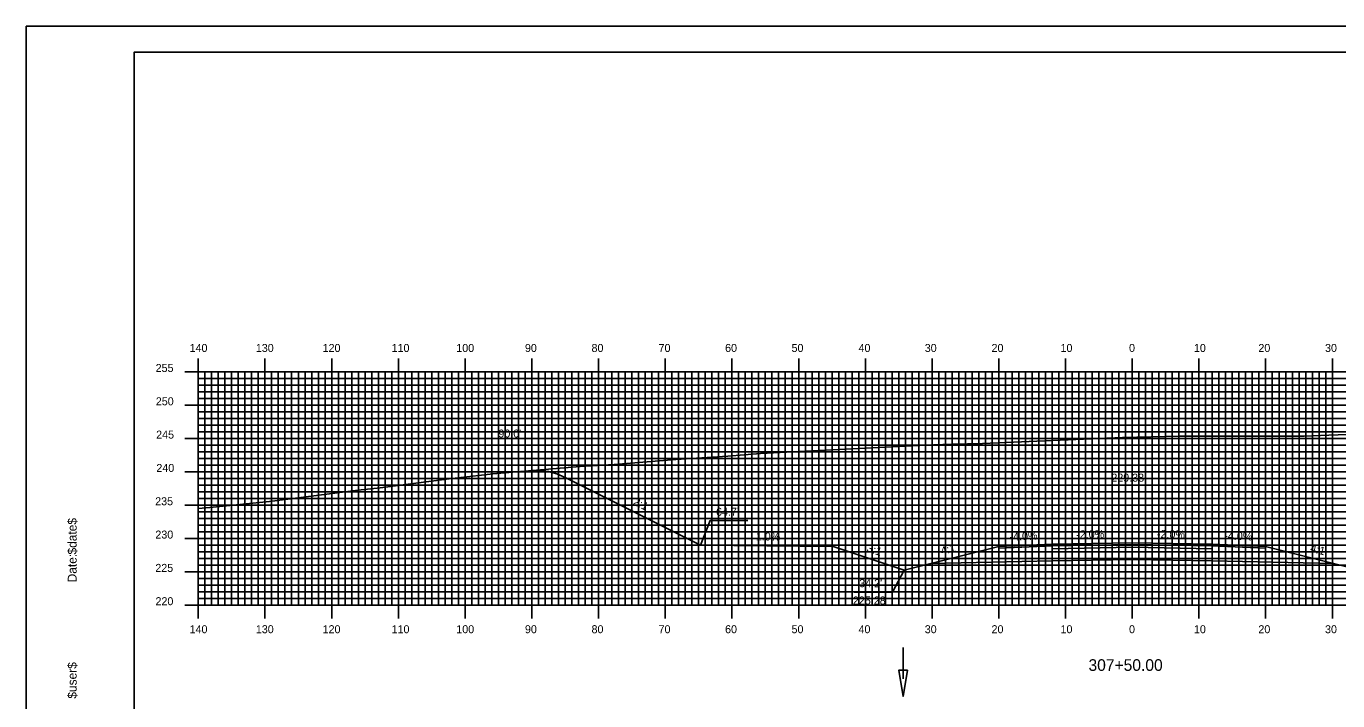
# Model space of a CAD drawing. Extents: x 1817276 to 1817620, y 442591 to 442811.
# Drawn here: x 1817276.3 to 1817472.9, y 442709.3 to 442810.5 of the extents above; entities that cross this region are included whole.
import ezdxf

# ---------------------------------------------------------------- set-up
doc = ezdxf.new("R2010")
doc.units = 0
for name, color, linetype in [('ANNOTATION', 7, 'Continuous'), ('BORDER', 7, 'Continuous'), ('D_Drainage_Ditch_Line', 7, 'Continuous'), ('D_Roadway_Centerline', 7, 'Continuous'), ('D_Roadway_Centerline_Text', 7, 'Continuous'), ('D_Roadway_Edge_Shoulder', 7, 'Continuous'), ('D_Roadway_Edge_TW', 7, 'Continuous'), ('D_Roadway_Pavement', 7, 'Continuous'), ('D_Roadway_SlopeLines', 7, 'Continuous'), ('D_Roadway_SubGrade', 7, 'Continuous'), ('D_Text_Standard', 7, 'Continuous'), ('H_V ANNOTATION', 7, 'Continuous'), ('MAJOR', 7, 'Continuous'), ('MINOR', 7, 'Continuous'), ('PLOT BOUNDARY', 7, 'Continuous'), ('S_Roadway_Centerline', 7, 'Continuous')]:
    doc.layers.add(name, color=color, linetype=linetype)

msp = doc.modelspace()

# ---------------------------------------------------------------- linework, layer by layer
at = {"layer": 'ANNOTATION'}
for points in [[(1817384.5, 442736.36), (1817378.81, 442736.36), (1817377.4, 442732.69)], [(1817400.44, 442725.65), (1817406.14, 442725.65), (1817407.93, 442728.94)]]:
    msp.add_lwpolyline(points, dxfattribs=at)
at = {"layer": 'BORDER'}
msp.add_lwpolyline([(1817292.5, 442596.67), (1817612.5, 442596.67), (1817612.5, 442806.67), (1817292.5, 442806.67)], close=True, dxfattribs=at)
at = {"layer": 'D_Drainage_Ditch_Line'}
msp.add_line((1817407.75, 442712.61), (1817407.75, 442717.31), dxfattribs=at)
msp.add_lwpolyline([(1817408.41, 442713.92), (1817407.1, 442713.92), (1817407.75, 442709.99)], close=True, dxfattribs=at)
at = {"layer": 'D_Roadway_Centerline'}
msp.add_lwpolyline([(1817352.1, 442743.88), (1817353.35, 442743.89), (1817354.6, 442743.72), (1817355.85, 442743.37), (1817357.1, 442742.84), (1817377.4, 442732.69), (1817397.29, 442732.49), (1817407.93, 442728.94), (1817411.93, 442729.94), (1817422.1, 442732.49), (1817430.1, 442732.81), (1817442.1, 442733.05), (1817454.1, 442732.81), (1817462.1, 442732.49), (1817472.27, 442729.94), (1817476.27, 442728.94), (1817486.9, 442732.49), (1817495.76, 442732.58), (1817527.1, 442748.25), (1817528.35, 442748.79), (1817529.6, 442749.19), (1817530.85, 442749.43), (1817532.1, 442749.51)], dxfattribs=at)
at = {"layer": 'D_Roadway_Edge_Shoulder'}
for points in [[(1817430.1, 442732.81), (1817422.1, 442732.49), (1817422.1, 442732.24), (1817430.1, 442732.56)], [(1817454.1, 442732.81), (1817462.1, 442732.49), (1817462.1, 442732.24), (1817454.1, 442732.56)]]:
    msp.add_lwpolyline(points, close=True, dxfattribs=at)
at = {"layer": 'D_Roadway_Edge_TW'}
msp.add_lwpolyline([(1817430.1, 442732.56), (1817430.1, 442732.81), (1817442.1, 442733.05), (1817454.1, 442732.81), (1817454.1, 442732.56), (1817442.1, 442732.8)], close=True, dxfattribs=at)
at = {"layer": 'D_Roadway_Pavement'}
msp.add_lwpolyline([(1817430.1, 442732.14), (1817430.1, 442732.56), (1817442.1, 442732.8), (1817454.1, 442732.56), (1817454.1, 442732.14), (1817442.1, 442732.38)], close=True, dxfattribs=at)
at = {"layer": 'D_Roadway_SlopeLines'}
for points in [[(1817397.29, 442732.49), (1817377.4, 442732.69), (1817357.1, 442742.84), (1817355.85, 442743.37), (1817354.6, 442743.72), (1817353.35, 442743.89), (1817352.1, 442743.88)], [(1817407.93, 442728.94), (1817397.29, 442732.49)], [(1817422.1, 442732.49), (1817407.93, 442728.94)], [(1817462.1, 442732.49), (1817476.27, 442728.94)]]:
    msp.add_lwpolyline(points, dxfattribs=at)
at = {"layer": 'D_Roadway_SubGrade'}
msp.add_lwpolyline([(1817430.1, 442730.31), (1817411.93, 442729.94), (1817422.1, 442732.49), (1817422.1, 442732.24), (1817430.1, 442732.56), (1817442.1, 442732.8), (1817454.1, 442732.56), (1817462.1, 442732.24), (1817462.1, 442732.49), (1817472.27, 442729.94), (1817454.1, 442730.31), (1817442.1, 442730.55)], close=True, dxfattribs=at)
at = {"layer": 'MAJOR'}
for p, q in [((1817302.1, 442760.67), (1817302.1, 442758.67)), ((1817312.1, 442760.67), (1817312.1, 442758.67)), ((1817322.1, 442760.67), (1817322.1, 442758.67)), ((1817332.1, 442760.67), (1817332.1, 442758.67)), ((1817342.1, 442760.67), (1817342.1, 442758.67)), ((1817352.1, 442760.67), (1817352.1, 442758.67)), ((1817362.1, 442760.67), (1817362.1, 442758.67)), ((1817372.1, 442760.67), (1817372.1, 442758.67)), ((1817382.1, 442760.67), (1817382.1, 442758.67)), ((1817392.1, 442760.67), (1817392.1, 442758.67)), ((1817402.1, 442760.67), (1817402.1, 442758.67)), ((1817412.1, 442760.67), (1817412.1, 442758.67)), ((1817422.1, 442760.67), (1817422.1, 442758.67)), ((1817432.1, 442760.67), (1817432.1, 442758.67)), ((1817442.1, 442760.67), (1817442.1, 442758.67)), ((1817452.1, 442760.67), (1817452.1, 442758.67)), ((1817462.1, 442760.67), (1817462.1, 442758.67)), ((1817472.1, 442760.67), (1817472.1, 442758.67)), ((1817300.1, 442758.67), (1817302.1, 442758.67)), ((1817302.1, 442758.67), (1817582.1, 442758.67)), ((1817302.1, 442723.67), (1817302.1, 442758.67)), ((1817302.1, 442723.67), (1817302.1, 442758.67)), ((1817302.1, 442758.67), (1817582.1, 442758.67)), ((1817312.1, 442723.67), (1817312.1, 442758.67)), ((1817322.1, 442723.67), (1817322.1, 442758.67)), ((1817332.1, 442723.67), (1817332.1, 442758.67)), ((1817342.1, 442723.67), (1817342.1, 442758.67)), ((1817352.1, 442723.67), (1817352.1, 442758.67)), ((1817362.1, 442723.67), (1817362.1, 442758.67)), ((1817372.1, 442723.67), (1817372.1, 442758.67)), ((1817382.1, 442723.67), (1817382.1, 442758.67)), ((1817392.1, 442723.67), (1817392.1, 442758.67)), ((1817402.1, 442723.67), (1817402.1, 442758.67)), ((1817412.1, 442723.67), (1817412.1, 442758.67)), ((1817422.1, 442723.67), (1817422.1, 442758.67)), ((1817432.1, 442723.67), (1817432.1, 442758.67)), ((1817442.1, 442723.67), (1817442.1, 442758.67)), ((1817452.1, 442723.67), (1817452.1, 442758.67)), ((1817462.1, 442723.67), (1817462.1, 442758.67)), ((1817472.1, 442723.67), (1817472.1, 442758.67)), ((1817300.1, 442753.67), (1817302.1, 442753.67)), ((1817302.1, 442753.67), (1817582.1, 442753.67)), ((1817300.1, 442748.67), (1817302.1, 442748.67)), ((1817302.1, 442748.67), (1817582.1, 442748.67)), ((1817300.1, 442743.67), (1817302.1, 442743.67)), ((1817302.1, 442743.67), (1817582.1, 442743.67)), ((1817300.1, 442738.67), (1817302.1, 442738.67)), ((1817302.1, 442738.67), (1817582.1, 442738.67)), ((1817300.1, 442733.67), (1817302.1, 442733.67)), ((1817302.1, 442733.67), (1817582.1, 442733.67)), ((1817300.1, 442728.67), (1817302.1, 442728.67)), ((1817302.1, 442728.67), (1817582.1, 442728.67)), ((1817300.1, 442723.67), (1817302.1, 442723.67)), ((1817302.1, 442723.67), (1817582.1, 442723.67)), ((1817302.1, 442723.67), (1817582.1, 442723.67)), ((1817302.1, 442721.66), (1817302.1, 442723.67)), ((1817312.1, 442721.66), (1817312.1, 442723.67)), ((1817322.1, 442721.66), (1817322.1, 442723.67)), ((1817332.1, 442721.66), (1817332.1, 442723.67)), ((1817342.1, 442721.66), (1817342.1, 442723.67)), ((1817352.1, 442721.66), (1817352.1, 442723.67)), ((1817362.1, 442721.66), (1817362.1, 442723.67)), ((1817372.1, 442721.66), (1817372.1, 442723.67)), ((1817382.1, 442721.66), (1817382.1, 442723.67)), ((1817392.1, 442721.66), (1817392.1, 442723.67)), ((1817402.1, 442721.66), (1817402.1, 442723.67)), ((1817412.1, 442721.66), (1817412.1, 442723.67)), ((1817422.1, 442721.66), (1817422.1, 442723.67)), ((1817432.1, 442721.66), (1817432.1, 442723.67)), ((1817442.1, 442721.66), (1817442.1, 442723.67)), ((1817452.1, 442721.66), (1817452.1, 442723.67)), ((1817462.1, 442721.66), (1817462.1, 442723.67)), ((1817472.1, 442721.66), (1817472.1, 442723.67))]:
    msp.add_line(p, q, dxfattribs=at)
at = {"layer": 'MINOR'}
for p, q in [((1817302.1, 442757.67), (1817582.1, 442757.67)), ((1817302.1, 442757.67), (1817304.1, 442757.67)), ((1817303.1, 442723.67), (1817303.1, 442758.67)), ((1817304.1, 442723.67), (1817304.1, 442758.67)), ((1817305.1, 442723.67), (1817305.1, 442758.67)), ((1817306.1, 442723.67), (1817306.1, 442758.67)), ((1817307.1, 442723.67), (1817307.1, 442758.67)), ((1817308.1, 442723.67), (1817308.1, 442758.67)), ((1817309.1, 442723.67), (1817309.1, 442758.67)), ((1817310.1, 442723.67), (1817310.1, 442758.67)), ((1817311.1, 442723.67), (1817311.1, 442758.67)), ((1817313.1, 442723.67), (1817313.1, 442758.67)), ((1817314.1, 442723.67), (1817314.1, 442758.67)), ((1817315.1, 442723.67), (1817315.1, 442758.67)), ((1817316.1, 442723.67), (1817316.1, 442758.67)), ((1817317.1, 442723.67), (1817317.1, 442758.67)), ((1817318.1, 442723.67), (1817318.1, 442758.67)), ((1817319.1, 442723.67), (1817319.1, 442758.67)), ((1817320.1, 442723.67), (1817320.1, 442758.67)), ((1817321.1, 442723.67), (1817321.1, 442758.67)), ((1817323.1, 442723.67), (1817323.1, 442758.67)), ((1817324.1, 442723.67), (1817324.1, 442758.67)), ((1817325.1, 442723.67), (1817325.1, 442758.67)), ((1817326.1, 442723.67), (1817326.1, 442758.67)), ((1817327.1, 442723.67), (1817327.1, 442758.67)), ((1817328.1, 442723.67), (1817328.1, 442758.67)), ((1817329.1, 442723.67), (1817329.1, 442758.67)), ((1817330.1, 442723.67), (1817330.1, 442758.67)), ((1817331.1, 442723.67), (1817331.1, 442758.67)), ((1817333.1, 442723.67), (1817333.1, 442758.67)), ((1817334.1, 442723.67), (1817334.1, 442758.67)), ((1817335.1, 442723.67), (1817335.1, 442758.67)), ((1817336.1, 442723.67), (1817336.1, 442758.67)), ((1817337.1, 442723.67), (1817337.1, 442758.67)), ((1817338.1, 442723.67), (1817338.1, 442758.67)), ((1817339.1, 442723.67), (1817339.1, 442758.67)), ((1817340.1, 442723.67), (1817340.1, 442758.67)), ((1817341.1, 442723.67), (1817341.1, 442758.67)), ((1817343.1, 442723.67), (1817343.1, 442758.67)), ((1817344.1, 442723.67), (1817344.1, 442758.67)), ((1817345.1, 442723.67), (1817345.1, 442758.67)), ((1817346.1, 442723.67), (1817346.1, 442758.67)), ((1817347.1, 442723.67), (1817347.1, 442758.67)), ((1817348.1, 442723.67), (1817348.1, 442758.67)), ((1817349.1, 442723.67), (1817349.1, 442758.67)), ((1817350.1, 442723.67), (1817350.1, 442758.67)), ((1817351.1, 442723.67), (1817351.1, 442758.67)), ((1817353.1, 442723.67), (1817353.1, 442758.67)), ((1817354.1, 442723.67), (1817354.1, 442758.67)), ((1817355.1, 442723.67), (1817355.1, 442758.67)), ((1817356.1, 442723.67), (1817356.1, 442758.67)), ((1817357.1, 442723.67), (1817357.1, 442758.67)), ((1817358.1, 442723.67), (1817358.1, 442758.67)), ((1817359.1, 442723.67), (1817359.1, 442758.67)), ((1817360.1, 442723.67), (1817360.1, 442758.67)), ((1817361.1, 442723.67), (1817361.1, 442758.67)), ((1817363.1, 442723.67), (1817363.1, 442758.67)), ((1817364.1, 442723.67), (1817364.1, 442758.67)), ((1817365.1, 442723.67), (1817365.1, 442758.67)), ((1817366.1, 442723.67), (1817366.1, 442758.67)), ((1817367.1, 442723.67), (1817367.1, 442758.67)), ((1817368.1, 442723.67), (1817368.1, 442758.67)), ((1817369.1, 442723.67), (1817369.1, 442758.67)), ((1817370.1, 442723.67), (1817370.1, 442758.67)), ((1817371.1, 442723.67), (1817371.1, 442758.67)), ((1817373.1, 442723.67), (1817373.1, 442758.67)), ((1817374.1, 442723.67), (1817374.1, 442758.67)), ((1817375.1, 442723.67), (1817375.1, 442758.67)), ((1817376.1, 442723.67), (1817376.1, 442758.67)), ((1817377.1, 442723.67), (1817377.1, 442758.67)), ((1817378.1, 442723.67), (1817378.1, 442758.67)), ((1817379.1, 442723.67), (1817379.1, 442758.67)), ((1817380.1, 442723.67), (1817380.1, 442758.67)), ((1817381.1, 442723.67), (1817381.1, 442758.67)), ((1817383.1, 442723.67), (1817383.1, 442758.67)), ((1817384.1, 442723.67), (1817384.1, 442758.67)), ((1817385.1, 442723.67), (1817385.1, 442758.67)), ((1817386.1, 442723.67), (1817386.1, 442758.67)), ((1817387.1, 442723.67), (1817387.1, 442758.67)), ((1817388.1, 442723.67), (1817388.1, 442758.67)), ((1817389.1, 442723.67), (1817389.1, 442758.67)), ((1817390.1, 442723.67), (1817390.1, 442758.67)), ((1817391.1, 442723.67), (1817391.1, 442758.67)), ((1817393.1, 442723.67), (1817393.1, 442758.67)), ((1817394.1, 442723.67), (1817394.1, 442758.67)), ((1817395.1, 442723.67), (1817395.1, 442758.67)), ((1817396.1, 442723.67), (1817396.1, 442758.67)), ((1817397.1, 442723.67), (1817397.1, 442758.67)), ((1817398.1, 442723.67), (1817398.1, 442758.67)), ((1817399.1, 442723.67), (1817399.1, 442758.67)), ((1817400.1, 442723.67), (1817400.1, 442758.67)), ((1817401.1, 442723.67), (1817401.1, 442758.67)), ((1817403.1, 442723.67), (1817403.1, 442758.67)), ((1817404.1, 442723.67), (1817404.1, 442758.67)), ((1817405.1, 442723.67), (1817405.1, 442758.67)), ((1817406.1, 442723.67), (1817406.1, 442758.67)), ((1817407.1, 442723.67), (1817407.1, 442758.67)), ((1817408.1, 442723.67), (1817408.1, 442758.67)), ((1817409.1, 442723.67), (1817409.1, 442758.67)), ((1817410.1, 442723.67), (1817410.1, 442758.67)), ((1817411.1, 442723.67), (1817411.1, 442758.67)), ((1817413.1, 442723.67), (1817413.1, 442758.67)), ((1817414.1, 442723.67), (1817414.1, 442758.67)), ((1817415.1, 442723.67), (1817415.1, 442758.67)), ((1817416.1, 442723.67), (1817416.1, 442758.67)), ((1817417.1, 442723.67), (1817417.1, 442758.67)), ((1817418.1, 442723.67), (1817418.1, 442758.67)), ((1817419.1, 442723.67), (1817419.1, 442758.67)), ((1817420.1, 442723.67), (1817420.1, 442758.67)), ((1817421.1, 442723.67), (1817421.1, 442758.67)), ((1817423.1, 442723.67), (1817423.1, 442758.67)), ((1817424.1, 442723.67), (1817424.1, 442758.67)), ((1817425.1, 442723.67), (1817425.1, 442758.67)), ((1817426.1, 442723.67), (1817426.1, 442758.67)), ((1817427.1, 442723.67), (1817427.1, 442758.67)), ((1817428.1, 442723.67), (1817428.1, 442758.67)), ((1817429.1, 442723.67), (1817429.1, 442758.67)), ((1817430.1, 442723.67), (1817430.1, 442758.67)), ((1817431.1, 442723.67), (1817431.1, 442758.67)), ((1817433.1, 442723.67), (1817433.1, 442758.67)), ((1817434.1, 442723.67), (1817434.1, 442758.67)), ((1817435.1, 442723.67), (1817435.1, 442758.67)), ((1817436.1, 442723.67), (1817436.1, 442758.67)), ((1817437.1, 442723.67), (1817437.1, 442758.67)), ((1817438.1, 442723.67), (1817438.1, 442758.67)), ((1817439.1, 442723.67), (1817439.1, 442758.67)), ((1817440.1, 442723.67), (1817440.1, 442758.67)), ((1817441.1, 442723.67), (1817441.1, 442758.67)), ((1817443.1, 442723.67), (1817443.1, 442758.67)), ((1817444.1, 442723.67), (1817444.1, 442758.67)), ((1817445.1, 442723.67), (1817445.1, 442758.67)), ((1817446.1, 442723.67), (1817446.1, 442758.67)), ((1817447.1, 442723.67), (1817447.1, 442758.67)), ((1817448.1, 442723.67), (1817448.1, 442758.67)), ((1817449.1, 442723.67), (1817449.1, 442758.67)), ((1817450.1, 442723.67), (1817450.1, 442758.67)), ((1817451.1, 442723.67), (1817451.1, 442758.67)), ((1817453.1, 442723.67), (1817453.1, 442758.67)), ((1817454.1, 442723.67), (1817454.1, 442758.67)), ((1817455.1, 442723.67), (1817455.1, 442758.67)), ((1817456.1, 442723.67), (1817456.1, 442758.67)), ((1817457.1, 442723.67), (1817457.1, 442758.67)), ((1817458.1, 442723.67), (1817458.1, 442758.67)), ((1817459.1, 442723.67), (1817459.1, 442758.67)), ((1817460.1, 442723.67), (1817460.1, 442758.67)), ((1817461.1, 442723.67), (1817461.1, 442758.67)), ((1817463.1, 442723.67), (1817463.1, 442758.67)), ((1817464.1, 442723.67), (1817464.1, 442758.67)), ((1817465.1, 442723.67), (1817465.1, 442758.67)), ((1817466.1, 442723.67), (1817466.1, 442758.67)), ((1817467.1, 442723.67), (1817467.1, 442758.67)), ((1817468.1, 442723.67), (1817468.1, 442758.67)), ((1817469.1, 442723.67), (1817469.1, 442758.67)), ((1817470.1, 442723.67), (1817470.1, 442758.67)), ((1817471.1, 442723.67), (1817471.1, 442758.67)), ((1817302.1, 442756.67), (1817582.1, 442756.67)), ((1817302.1, 442756.67), (1817304.1, 442756.67)), ((1817302.1, 442755.67), (1817582.1, 442755.67)), ((1817302.1, 442755.67), (1817304.1, 442755.67)), ((1817302.1, 442754.67), (1817582.1, 442754.67)), ((1817302.1, 442754.67), (1817304.1, 442754.67)), ((1817302.1, 442752.67), (1817582.1, 442752.67)), ((1817302.1, 442752.67), (1817304.1, 442752.67)), ((1817302.1, 442751.67), (1817582.1, 442751.67)), ((1817302.1, 442751.67), (1817304.1, 442751.67)), ((1817302.1, 442750.67), (1817582.1, 442750.67)), ((1817302.1, 442750.67), (1817304.1, 442750.67)), ((1817302.1, 442749.67), (1817582.1, 442749.67)), ((1817302.1, 442749.67), (1817304.1, 442749.67)), ((1817302.1, 442747.67), (1817582.1, 442747.67)), ((1817302.1, 442747.67), (1817304.1, 442747.67)), ((1817302.1, 442746.67), (1817582.1, 442746.67)), ((1817302.1, 442746.67), (1817304.1, 442746.67)), ((1817302.1, 442745.67), (1817582.1, 442745.67)), ((1817302.1, 442745.67), (1817304.1, 442745.67)), ((1817302.1, 442744.67), (1817582.1, 442744.67)), ((1817302.1, 442744.67), (1817304.1, 442744.67)), ((1817302.1, 442742.67), (1817582.1, 442742.67)), ((1817302.1, 442742.67), (1817304.1, 442742.67)), ((1817302.1, 442741.67), (1817582.1, 442741.67)), ((1817302.1, 442741.67), (1817304.1, 442741.67)), ((1817302.1, 442740.67), (1817582.1, 442740.67)), ((1817302.1, 442740.67), (1817304.1, 442740.67)), ((1817302.1, 442739.67), (1817582.1, 442739.67)), ((1817302.1, 442739.67), (1817304.1, 442739.67)), ((1817302.1, 442737.67), (1817582.1, 442737.67)), ((1817302.1, 442737.67), (1817304.1, 442737.67)), ((1817302.1, 442736.67), (1817582.1, 442736.67)), ((1817302.1, 442736.67), (1817304.1, 442736.67)), ((1817302.1, 442735.67), (1817582.1, 442735.67)), ((1817302.1, 442735.67), (1817304.1, 442735.67)), ((1817302.1, 442734.67), (1817582.1, 442734.67)), ((1817302.1, 442734.67), (1817304.1, 442734.67)), ((1817302.1, 442732.67), (1817582.1, 442732.67)), ((1817302.1, 442732.67), (1817304.1, 442732.67)), ((1817302.1, 442731.67), (1817582.1, 442731.67)), ((1817302.1, 442731.67), (1817304.1, 442731.67)), ((1817302.1, 442730.67), (1817582.1, 442730.67)), ((1817302.1, 442730.67), (1817304.1, 442730.67)), ((1817302.1, 442729.67), (1817582.1, 442729.67)), ((1817302.1, 442729.67), (1817304.1, 442729.67)), ((1817302.1, 442727.67), (1817582.1, 442727.67)), ((1817302.1, 442727.67), (1817304.1, 442727.67)), ((1817302.1, 442726.67), (1817582.1, 442726.67)), ((1817302.1, 442726.67), (1817304.1, 442726.67)), ((1817302.1, 442725.67), (1817582.1, 442725.67)), ((1817302.1, 442725.67), (1817304.1, 442725.67)), ((1817302.1, 442724.67), (1817582.1, 442724.67)), ((1817302.1, 442724.67), (1817304.1, 442724.67))]:
    msp.add_line(p, q, dxfattribs=at)
at = {"layer": 'PLOT BOUNDARY'}
msp.add_lwpolyline([(1817276.31, 442590.55), (1817616.31, 442590.55), (1817616.31, 442810.55), (1817276.31, 442810.55)], close=True, dxfattribs=at)
at = {"layer": 'S_Roadway_Centerline'}
msp.add_lwpolyline([(1817302.1, 442738.16), (1817303.84, 442738.35), (1817312.77, 442739.23), (1817326.07, 442740.94), (1817329.36, 442741.27), (1817339.7, 442742.61), (1817345.02, 442743.24), (1817346.26, 442743.4), (1817359.37, 442744.47), (1817364.45, 442744.8), (1817373.7, 442745.52), (1817381.48, 442746.06), (1817386.38, 442746.44), (1817403.01, 442747.27), (1817412.29, 442747.75), (1817415.13, 442747.83), (1817419.65, 442747.96), (1817440.64, 442748.85), (1817449.2, 442749.02), (1817465.2, 442749.04), (1817466.91, 442749.05), (1817467.86, 442749.06), (1817471.56, 442749.19), (1817482.76, 442749.6)], dxfattribs=at)

# ---------------------------------------------------------------- texts
at = {"layer": 'ANNOTATION'}
for s, rotation, p in [('2:1', 333.4349, (1817367.18, 442738.83)), ('1.0%', 359.4271, (1817385.68, 442733.4)), ('-4.0%', 2.2906, (1817423.73, 442733.35)), ('-2.0%', 1.1458, (1817433.71, 442733.68)), ('-2.0%', 358.8542, (1817445.79, 442733.77)), ('-4.0%', 357.7094, (1817455.89, 442733.54)), ('3:1', 341.5651, (1817402.21, 442731.76)), ('4:1', 14.0362, (1817413.55, 442731.21)), ('4:1', 345.9638, (1817468.69, 442731.7))]:
    msp.add_text(s, height=1.2, rotation=rotation, dxfattribs=at).set_placement(p)
for s, p in [("64.7'", (1817379.72, 442737.09)), ("34.2'", (1817401.18, 442726.38)), ('225.28', (1817400.23, 442723.78))]:
    msp.add_text(s, height=1.2, dxfattribs=at).set_placement(p)
at = {"layer": 'BORDER'}
for s, p in [('$date$', (1817283.87, 442731.28)), ('Date:', (1817283.87, 442727.1)), ('$user$', (1817283.87, 442709.65))]:
    msp.add_text(s, height=1.339, rotation=90, dxfattribs=at).set_placement(p)
at = {"layer": 'D_Roadway_Centerline'}
for s, p in [('C', (1817442.09, 442733.05)), ('L', (1817442.1, 442733.04))]:
    msp.add_text(s, height=0.0146, dxfattribs=at).set_placement(p)
at = {"layer": 'D_Roadway_Centerline_Text'}
msp.add_text('229.38', height=1.2, dxfattribs=at).set_placement((1817438.97, 442742.21))
at = {"layer": 'D_Text_Standard'}
msp.add_text("90.0'", height=1.2, dxfattribs=at).set_placement((1817347.09, 442748.83))
at = {"layer": 'H_V ANNOTATION'}
for s, height, p in [('140', 1.2, (1817300.8, 442761.67)), ('130', 1.2, (1817310.73, 442761.67)), ('120', 1.2, (1817320.74, 442761.67)), ('110', 1.2, (1817331.08, 442761.67)), ('100', 1.2, (1817340.78, 442761.67)), ('90', 1.2, (1817351.07, 442761.67)), ('80', 1.2, (1817361.05, 442761.67)), ('70', 1.2, (1817371.1, 442761.67)), ('60', 1.2, (1817381.07, 442761.67)), ('50', 1.2, (1817391.03, 442761.67)), ('40', 1.2, (1817401.07, 442761.67)), ('30', 1.2, (1817411, 442761.67)), ('20', 1.2, (1817421.01, 442761.67)), ('10', 1.2, (1817431.35, 442761.67)), ('0', 1.2, (1817441.62, 442761.67)), ('10', 1.2, (1817451.35, 442761.67)), ('20', 1.2, (1817461.01, 442761.67)), ('30', 1.2, (1817471, 442761.67)), ('255', 1.2, (1817295.71, 442758.67)), ('250', 1.2, (1817295.74, 442753.67)), ('245', 1.2, (1817295.79, 442748.67)), ('240', 1.2, (1817295.82, 442743.67)), ('235', 1.2, (1817295.64, 442738.67)), ('230', 1.2, (1817295.67, 442733.67)), ('225', 1.2, (1817295.66, 442728.67)), ('220', 1.2, (1817295.69, 442723.67)), ('140', 1.2, (1817300.8, 442719.47)), ('130', 1.2, (1817310.73, 442719.47)), ('120', 1.2, (1817320.74, 442719.47)), ('110', 1.2, (1817331.08, 442719.47)), ('100', 1.2, (1817340.78, 442719.47)), ('90', 1.2, (1817351.07, 442719.47)), ('80', 1.2, (1817361.05, 442719.47)), ('70', 1.2, (1817371.1, 442719.47)), ('60', 1.2, (1817381.07, 442719.47)), ('50', 1.2, (1817391.03, 442719.47)), ('40', 1.2, (1817401.07, 442719.47)), ('30', 1.2, (1817411, 442719.47)), ('20', 1.2, (1817421.01, 442719.47)), ('10', 1.2, (1817431.35, 442719.47)), ('0', 1.2, (1817441.62, 442719.47)), ('10', 1.2, (1817451.35, 442719.47)), ('20', 1.2, (1817461.01, 442719.47)), ('30', 1.2, (1817471, 442719.47)), ('307+50.00', 1.75, (1817435.54, 442713.82))]:
    msp.add_text(s, height=height, dxfattribs=at).set_placement(p)
at = {"layer": 'MAJOR'}
msp.add_text('-', height=0.012, dxfattribs=at).set_placement((1817302.09, 442723.67))

doc.saveas('drawing.dxf')
